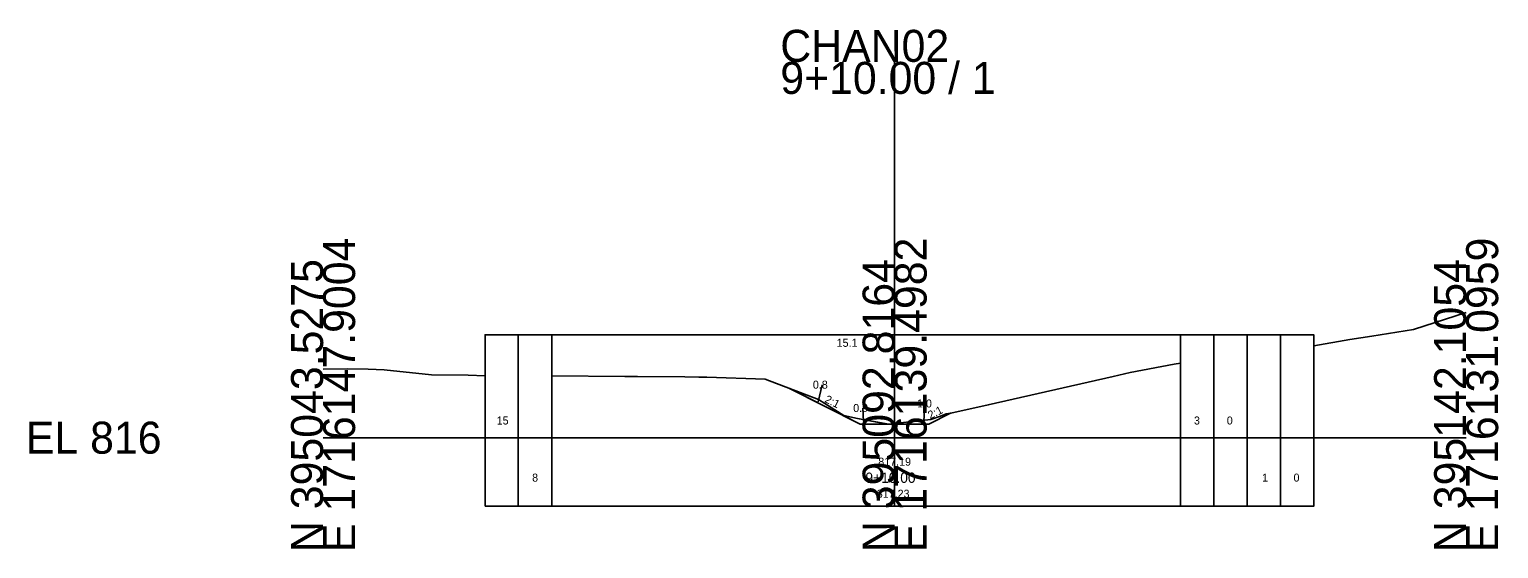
# Model space of a CAD drawing. Extents: x -26 to 103, y -10 to 16052.
# Drawn here: x -25.7 to 102.8, y 1990.3 to 2035.7 of the extents above; entities that cross this region are included whole.
import ezdxf

# ---------------------------------------------------------------- set-up
doc = ezdxf.new("R2010")
doc.units = 0
for name, color, linetype in [('GK_Cells', 7, 'Continuous'), ('SH_Text', 7, 'Continuous'), ('XS_P_Annotation', 7, 'Continuous'), ('XS_P_Boundary', 7, 'Continuous'), ('XS_P_Earthwork_Shapes', 7, 'Continuous'), ('XS_P_Finished_Grade', 7, 'Continuous'), ('XS_X_Ground_Line', 7, 'Continuous')]:
    doc.layers.add(name, color=color, linetype=linetype)

msp = doc.modelspace()

# ---------------------------------------------------------------- linework, layer by layer
at = {"layer": 'GK_Cells'}
for p, q in [((50, 2000), (50, 2032.84)), ((0, 2000), (50, 2000)), ((50, 2000), (100, 2000))]:
    msp.add_line(p, q, dxfattribs=at)
at = {"layer": 'XS_P_Boundary'}
for p, q in [((17.08, 1994.01), (17.08, 2008.99)), ((20, 1994.01), (20, 2008.99)), ((50, 1994.01), (50, 2008.99)), ((75, 1994.01), (75, 2008.99)), ((77.92, 1994.01), (77.92, 2008.99)), ((80.83, 1994.01), (80.83, 2008.99)), ((83.75, 1994.01), (83.75, 2008.99)), ((15.63, 2001.5), (15.63, 2001.5)), ((76.46, 2001.5), (76.46, 2001.5)), ((79.38, 2001.5), (79.38, 2001.5)), ((18.54, 1996.51), (18.54, 1996.51)), ((82.29, 1996.51), (82.29, 1996.51)), ((85.21, 1996.51), (85.21, 1996.51))]:
    msp.add_line(p, q, dxfattribs=at)
msp.add_lwpolyline([(14.17, 1994.01), (14.17, 2008.99), (86.67, 2008.99), (86.67, 1994.01)], close=True, dxfattribs=at)
at = {"layer": 'XS_P_Earthwork_Shapes'}
for p, q in [((40.74, 2004.32), (45.55, 2001.91)), ((43.3, 2003.14), (43.67, 2004.63)), ((47.28, 2001.44), (47.21, 2002.59)), ((52.55, 2001.44), (52.63, 2002.99)), ((45.55, 2001.91), (47, 2001.19)), ((46.75, 2001.68), (45.57, 2001.95)), ((49.39, 2001.19), (46.75, 2001.68)), ((53, 2001.19), (54.89, 2002.13)), ((47, 2001.19), (49.39, 2001.19)), ((50, 2001.19), (53, 2001.19))]:
    msp.add_line(p, q, dxfattribs=at)
for points in [[(45.57, 2001.95), (43.33, 2003.33), (40.74, 2004.32)], [(40.74, 2004.32), (47, 2001.19), (53, 2001.19), (54.89, 2002.13)], [(45.57, 2001.95), (45.55, 2001.91)], [(45.55, 2001.91), (45.57, 2001.95)], [(54.89, 2002.13), (54.51, 2002.07), (54, 2001.88), (53.18, 2001.59), (50, 2001.23)], [(50, 2001.23), (50, 2001.19)]]:
    msp.add_lwpolyline(points, dxfattribs=at)
at = {"layer": 'XS_P_Finished_Grade'}
for p, q in [((40.74, 2004.32), (47, 2001.19)), ((54.89, 2002.13), (53, 2001.19)), ((47, 2001.19), (53, 2001.19))]:
    msp.add_line(p, q, dxfattribs=at)
at = {"layer": 'XS_X_Ground_Line'}
for points in [[(86.67, 2008.03), (89.83, 2008.58), (91.75, 2008.88), (95.39, 2009.45), (100, 2010.95)], [(20, 2005.4), (26.4, 2005.35), (26.85, 2005.35), (27.52, 2005.34), (31.66, 2005.31), (32.86, 2005.3), (33.58, 2005.29), (38.69, 2005.1), (43.33, 2003.33), (45.57, 2001.95), (46.75, 2001.68), (49.48, 2001.17), (50, 2001.23), (53.18, 2001.59), (54, 2001.88), (54.51, 2002.07), (54.93, 2002.14), (58.19, 2002.86), (69.12, 2005.35), (70.62, 2005.7), (74.45, 2006.41), (75, 2006.51)], [(0, 2005.98), (2.18, 2006.01), (3.95, 2005.98), (5.34, 2005.94), (9.48, 2005.5), (12.69, 2005.45), (14.17, 2005.41)]]:
    msp.add_lwpolyline(points, dxfattribs=at)

# ---------------------------------------------------------------- texts
at = {"layer": 'GK_Cells'}
for s, p in [('CHAN02', (40, 2032.84)), ('9+10.00 / 1', (40, 2030.04)), ('EL 816', (-26, 1998.6))]:
    msp.add_text(s, height=2.8, dxfattribs=at).set_placement(p)
for s, p in [('E 1716147.9004', (2.8, 1990)), ('E 1716139.4982', (52.8, 1990)), ('E 1716131.0959', (102.8, 1990)), ('N 395043.5275', (0, 1990)), ('N 395092.8164', (50, 1990)), ('N 395142.1054', (100, 1990))]:
    msp.add_text(s, height=2.8, rotation=90, dxfattribs=at).set_placement(p)
at = {"layer": 'SH_Text'}
for s, p in [('15', (15.19, 2001.15)), ('3', (76.19, 2001.15)), ('0', (79.06, 2001.15)), ('8', (18.29, 1996.16)), ('1', (82.15, 1996.16)), ('0', (84.9, 1996.16))]:
    msp.add_text(s, height=0.7, dxfattribs=at).set_placement(p)
at = {"layer": 'XS_P_Annotation'}
for rotation, p in [(333.4349, (43.82, 2003.13)), (26.5651, (53.12, 2001.6))]:
    msp.add_text('2:1', height=0.7, rotation=rotation, dxfattribs=at).set_placement(p)
for s, height, p in [('817.19', 0.7, (48.57, 1997.55)), ('9+10.00', 0.9, (47.45, 1996.05)), ('817.23', 0.7, (48.44, 1994.75))]:
    msp.add_text(s, height=height, dxfattribs=at).set_placement(p)
at = {"layer": 'XS_P_Earthwork_Shapes'}
for s, p in [('15.1', (44.93, 2007.94)), ('0.8', (42.85, 2004.28)), ('0.9', (46.38, 2002.24)), ('1.0', (51.96, 2002.64))]:
    msp.add_text(s, height=0.7, dxfattribs=at).set_placement(p)

doc.saveas('drawing.dxf')
